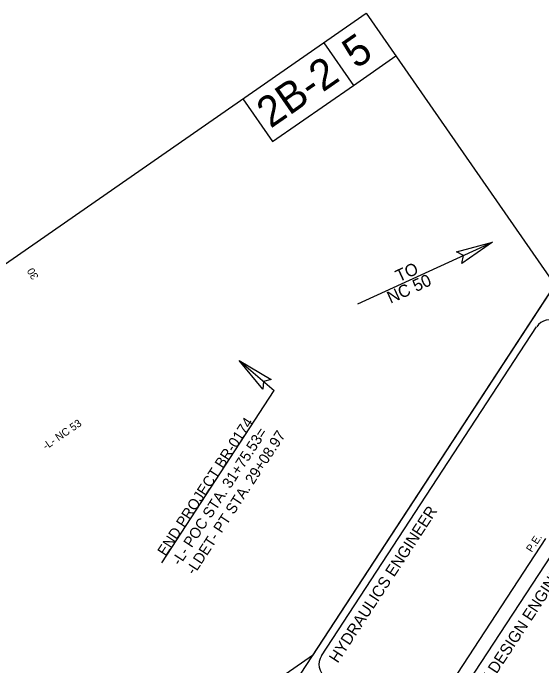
# Model space of a CAD drawing. Extents: x 1190029 to 2382315, y 163128 to 334830.
# Drawn here: x 2380933 to 2381627, y 332651 to 333507 of the extents above; entities that cross this region are included whole.
import ezdxf

# ---------------------------------------------------------------- set-up
doc = ezdxf.new("R2010")
doc.units = 0
for name, color, linetype in [('Exist Property Line', 7, 'Continuous'), ('Exist Utilities Telephone UG FO SUE LOS B Text', 7, 'Continuous'), ('P_NCDOT_Vertical_Profile_Grade_Label', 7, 'Continuous'), ('P_NCDOT_Vertical_Profile_Grade_Sheet_Elevation_Label', 7, 'Continuous'), ('Scratch_Level_4', 7, 'Continuous'), ('Sheet Block Title CELL', 7, 'Continuous'), ('Sheet_Plan_CELL', 7, 'Continuous')]:
    doc.layers.add(name, color=color, linetype=linetype)

msp = doc.modelspace()

# ---------------------------------------------------------------- linework, layer by layer
at = {"layer": 'Exist Utilities Telephone UG FO SUE LOS B Text'}
for p, q in [((2380185.48, 330920.12), (2381876.33, 333506.45)), ((2381337.5, 332663.99), (2381619.52, 333095.36)), ((2381477.22, 332548.75), (2381781.12, 333013.61)), ((2381476.53, 332580.86), (2381631.41, 332817.72))]:
    msp.add_line(p, q, dxfattribs=at)
for centre, start, end in [((2381636.35, 333084.35), 56.82484, 146.82484), ((2381354.17, 332653.1), 146.82484, 236.82484)]:
    msp.add_arc(centre, 20, start, end, dxfattribs=at)
at = {"layer": 'Scratch_Level_4'}
msp.add_line((2381385.21, 333125.23), (2381561.75, 333206.28), dxfattribs=at)
at = {"layer": 'Sheet Block Title CELL'}
for points in [[(2381514.68, 333193.77), (2381561.75, 333206.28), (2381521.45, 333178.39), (2381523.46, 333188.7)], [(2381260.57, 333013.58), (2381229.5, 333051.09), (2381271.7, 333026.16), (2381261.49, 333023.67)]]:
    msp.add_lwpolyline(points, close=True, dxfattribs=at)
at = {"layer": 'Sheet_Plan_CELL'}
for p in [(2381229.5, 333051.09), (2381128.21, 332785.95)]:
    msp.add_line(p, (2381275.57, 333011.61), dxfattribs=at)
msp.add_lwpolyline([(2380382.48, 332802.63), (2381396.26, 333506.53), (2381643.54, 333150.39), (2381325.79, 332664.35), (2380871.89, 332349.19)], close=True, dxfattribs=at)
for points in [[(2381340.35, 333467.71), (2381379.23, 333411.7), (2381435.15, 333450.53)], [(2381234.49, 333394.21), (2381273.38, 333338.21), (2381379.23, 333411.7)]]:
    msp.add_lwpolyline(points, dxfattribs=at)

# ---------------------------------------------------------------- texts
at = {"layer": 'Exist Property Line'}
msp.add_text('30', height=10, rotation=120.5372, dxfattribs=at).set_placement((2380966.9, 333160.88))
at = {"layer": 'Exist Utilities Telephone UG FO SUE LOS B Text'}
for s, height, p in [(' HYDRAULICS ENGINEER', 15, (2381355.72, 332648.87)), ('P.E.', 9.999, (2381613.31, 332798.85)), ('ROADWAY DESIGN ENGINEER', 14.9988, (2381507.32, 332548.13))]:
    msp.add_text(s, height=height, rotation=56.82484, dxfattribs=at).set_placement(p)
at = {"layer": 'P_NCDOT_Vertical_Profile_Grade_Label'}
msp.add_text('-L- NC 53', height=10, rotation=34.50644, dxfattribs=at).set_placement((2380976.21, 332933.71))
at = {"layer": 'P_NCDOT_Vertical_Profile_Grade_Sheet_Elevation_Label'}
for s, p in [('5', (2381382.94, 333432.59)), ('2B-2', (2381270.74, 333354.68))]:
    msp.add_text(s, height=40, rotation=34.77363, dxfattribs=at).set_placement(p)
at = {"layer": 'Sheet_Plan_CELL'}
for s, height, rotation, p in [('TO', 16, 24.65973, (2381439.04, 333153.51)), ('NC 50', 16, 24.65973, (2381428.02, 333125.37)), ('END PROJECT BR-0174', 14.0001, 56.82483, (2381133.1, 332793.66)), ('-L- POC STA. 31+75.53=', 14.0001, 56.82483, (2381151.85, 332781.4)), ('-LDET- PT STA. 29+08.97', 14.0001, 56.82483, (2381170.6, 332769.15))]:
    msp.add_text(s, height=height, rotation=rotation, dxfattribs=at).set_placement(p)

doc.saveas('drawing.dxf')
